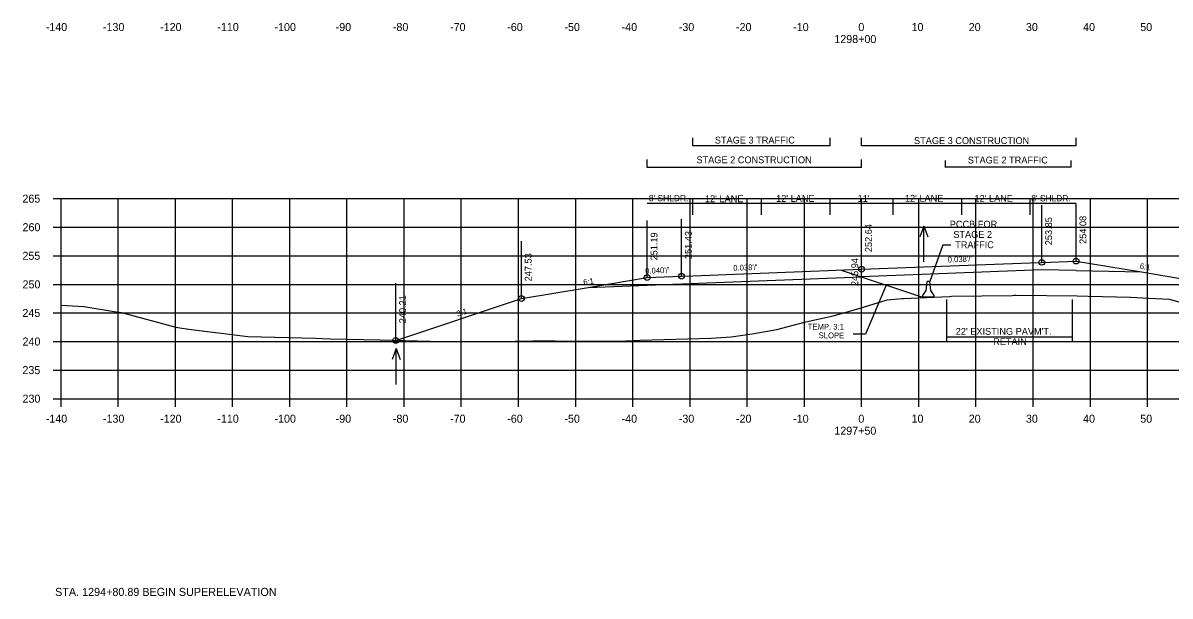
# Model space of a CAD drawing. Extents: x 1342547 to 1344156, y -1532351 to -1517216.
# Drawn here: x 1342556.2 to 1342756.8, y -1520418.8 to -1520318.5 of the extents above; entities that cross this region are included whole.
import ezdxf

# ---------------------------------------------------------------- set-up
doc = ezdxf.new("R2010")
doc.units = 0
for name, color, linetype in [('R_Alt Surface', 7, 'Continuous'), ('R_Axis', 7, 'Continuous'), ('R_Axis Annot', 7, 'Continuous'), ('R_Border Notes', 7, 'Continuous'), ('R_Draft', 7, 'Continuous'), ('R_Exist Surface', 7, 'Continuous'), ('R_Fin Surface', 7, 'Continuous'), ('R_Grid', 7, 'Continuous'), ('R_MOT', 7, 'Continuous'), ('R_No Plot', 7, 'Continuous'), ('R_Water', 7, 'Continuous'), ('R_Xsect Elev', 7, 'Continuous'), ('R_Xsect Slope', 7, 'Continuous')]:
    doc.layers.add(name, color=color, linetype=linetype)

msp = doc.modelspace()

# ---------------------------------------------------------------- linework, layer by layer
at = {"layer": 'R_Alt Surface'}
msp.add_line((1342734.37, -1520361.7), (1342702.87, -1520362.91), dxfattribs=at)
for points in [[(1342665.37, -1520364.35), (1342671.37, -1520364.12), (1342702.87, -1520362.91)], [(1342740.37, -1520361.82), (1342734.37, -1520361.7)], [(1342740.37, -1520361.82), (1342751.84, -1520362.05)], [(1342655.05, -1520364.75), (1342665.37, -1520364.35)]]:
    msp.add_lwpolyline(points, dxfattribs=at)
at = {"layer": 'R_Axis'}
for p, q in [((1342561.47, -1520349.22), (1342562.87, -1520349.22)), ((1342562.87, -1520384.22), (1342562.87, -1520349.22)), ((1342561.47, -1520354.22), (1342562.87, -1520354.22)), ((1342561.47, -1520359.22), (1342562.87, -1520359.22)), ((1342561.47, -1520364.22), (1342562.87, -1520364.22)), ((1342561.47, -1520369.22), (1342562.87, -1520369.22)), ((1342561.47, -1520374.22), (1342562.87, -1520374.22)), ((1342561.47, -1520379.22), (1342562.87, -1520379.22)), ((1342561.47, -1520384.22), (1342562.87, -1520384.22)), ((1342562.87, -1520384.22), (1342842.87, -1520384.22)), ((1342562.87, -1520385.62), (1342562.87, -1520384.22)), ((1342572.87, -1520385.62), (1342572.87, -1520384.22)), ((1342582.87, -1520385.62), (1342582.87, -1520384.22)), ((1342592.87, -1520385.62), (1342592.87, -1520384.22)), ((1342602.87, -1520385.62), (1342602.87, -1520384.22)), ((1342612.87, -1520385.62), (1342612.87, -1520384.22)), ((1342622.87, -1520385.62), (1342622.87, -1520384.22)), ((1342632.87, -1520385.62), (1342632.87, -1520384.22)), ((1342642.87, -1520385.62), (1342642.87, -1520384.22)), ((1342652.87, -1520385.62), (1342652.87, -1520384.22)), ((1342662.87, -1520385.62), (1342662.87, -1520384.22)), ((1342672.87, -1520385.62), (1342672.87, -1520384.22)), ((1342682.87, -1520385.62), (1342682.87, -1520384.22)), ((1342692.87, -1520385.62), (1342692.87, -1520384.22)), ((1342702.87, -1520385.62), (1342702.87, -1520384.22)), ((1342712.87, -1520385.62), (1342712.87, -1520384.22)), ((1342722.87, -1520385.62), (1342722.87, -1520384.22)), ((1342732.87, -1520385.62), (1342732.87, -1520384.22)), ((1342742.87, -1520385.62), (1342742.87, -1520384.22)), ((1342752.87, -1520385.62), (1342752.87, -1520384.22))]:
    msp.add_line(p, q, dxfattribs=at)
at = {"layer": 'R_Draft'}
for p, q in [((1342673.38, -1520340), (1342673.38, -1520338.57)), ((1342697.38, -1520340), (1342697.38, -1520338.57)), ((1342702.87, -1520340), (1342702.87, -1520338.57)), ((1342740.38, -1520340), (1342740.38, -1520338.57)), ((1342697.38, -1520340), (1342673.38, -1520340)), ((1342740.38, -1520340), (1342702.87, -1520340)), ((1342665.37, -1520343.8), (1342665.37, -1520342.36)), ((1342702.87, -1520343.8), (1342702.87, -1520342.36)), ((1342717.53, -1520343.8), (1342717.53, -1520342.56)), ((1342739.53, -1520343.7), (1342739.53, -1520342.56)), ((1342702.87, -1520343.8), (1342665.37, -1520343.8)), ((1342739.53, -1520343.7), (1342717.53, -1520343.7)), ((1342699.28, -1520361.72), (1342713.7, -1520366.53)), ((1342717.69, -1520366.88), (1342717.69, -1520374.08)), ((1342739.69, -1520366.88), (1342739.69, -1520374.08)), ((1342717.69, -1520373.41), (1342739.69, -1520373.41))]:
    msp.add_line(p, q, dxfattribs=at)
for points in [[(1342717.05, -1520357.32), (1342714.82, -1520363.73)], [(1342717.05, -1520357.32), (1342718.49, -1520357.32)]]:
    msp.add_lwpolyline(points, dxfattribs=at)
at = {"layer": 'R_Exist Surface'}
msp.add_lwpolyline([(1342562.87, -1520367.88), (1342566.86, -1520368.07), (1342572.17, -1520368.94), (1342573.42, -1520369.16), (1342582.95, -1520371.69), (1342583.62, -1520371.85), (1342585.21, -1520372.06), (1342595.52, -1520373.35), (1342607.35, -1520373.66), (1342608.56, -1520373.69), (1342610.02, -1520373.72), (1342618.62, -1520373.95), (1342627.45, -1520374.15), (1342640.08, -1520374.2), (1342644.52, -1520374.12), (1342645.01, -1520374.14), (1342645.38, -1520374.09), (1342645.47, -1520374.1), (1342645.55, -1520374.14), (1342645.68, -1520374.11), (1342649.28, -1520374.08), (1342649.63, -1520374.16), (1342661.57, -1520374.11), (1342664.14, -1520373.98), (1342676.55, -1520373.63), (1342680.06, -1520373.4), (1342683.73, -1520372.88), (1342688.04, -1520372.11), (1342693.09, -1520370.78), (1342697.92, -1520369.71), (1342702.6, -1520368.36), (1342707.34, -1520366.92), (1342709.94, -1520366.7), (1342710.2, -1520366.68), (1342718.23, -1520366.32), (1342718.61, -1520366.3), (1342729.18, -1520366.14), (1342729.55, -1520366.13), (1342729.92, -1520366.13), (1342740.56, -1520366.21), (1342742.49, -1520366.27), (1342749.93, -1520366.47), (1342749.93, -1520366.47), (1342753.04, -1520366.63), (1342756.71, -1520366.82), (1342764.98, -1520369.22)], dxfattribs=at)
at = {"layer": 'R_Fin Surface'}
msp.add_lwpolyline([(1342621.4, -1520374.02), (1342643.37, -1520366.69), (1342655.05, -1520364.75), (1342665.37, -1520363.03), (1342671.37, -1520362.79), (1342673.37, -1520362.71), (1342702.87, -1520361.58), (1342732.37, -1520360.45), (1342734.37, -1520360.37), (1342740.37, -1520360.14), (1342751.84, -1520362.05), (1342762.37, -1520363.81), (1342790.77, -1520373.27)], dxfattribs=at)
at = {"layer": 'R_Grid'}
for p, q in [((1342562.87, -1520349.22), (1342842.87, -1520349.22)), ((1342562.87, -1520384.22), (1342562.87, -1520349.22)), ((1342572.87, -1520384.22), (1342572.87, -1520349.22)), ((1342582.87, -1520384.22), (1342582.87, -1520349.22)), ((1342592.87, -1520384.22), (1342592.87, -1520349.22)), ((1342602.87, -1520384.22), (1342602.87, -1520349.22)), ((1342612.87, -1520384.22), (1342612.87, -1520349.22)), ((1342622.87, -1520384.22), (1342622.87, -1520349.22)), ((1342632.87, -1520384.22), (1342632.87, -1520349.22)), ((1342642.87, -1520384.22), (1342642.87, -1520349.22)), ((1342652.87, -1520384.22), (1342652.87, -1520349.22)), ((1342662.87, -1520384.22), (1342662.87, -1520349.22)), ((1342672.87, -1520384.22), (1342672.87, -1520349.22)), ((1342682.87, -1520384.22), (1342682.87, -1520349.22)), ((1342692.87, -1520384.22), (1342692.87, -1520349.22)), ((1342702.87, -1520384.22), (1342702.87, -1520349.22)), ((1342712.87, -1520384.22), (1342712.87, -1520349.22)), ((1342722.87, -1520384.22), (1342722.87, -1520349.22)), ((1342732.87, -1520384.22), (1342732.87, -1520349.22)), ((1342742.87, -1520384.22), (1342742.87, -1520349.22)), ((1342752.87, -1520384.22), (1342752.87, -1520349.22)), ((1342562.87, -1520354.22), (1342842.87, -1520354.22)), ((1342562.87, -1520359.22), (1342842.87, -1520359.22)), ((1342562.87, -1520364.22), (1342842.87, -1520364.22)), ((1342562.87, -1520369.22), (1342842.87, -1520369.22)), ((1342562.87, -1520374.22), (1342842.87, -1520374.22)), ((1342562.87, -1520379.22), (1342842.87, -1520379.22)), ((1342562.87, -1520384.22), (1342842.87, -1520384.22))]:
    msp.add_line(p, q, dxfattribs=at)
at = {"layer": 'R_MOT'}
for p, q in [((1342713.58, -1520366.15), (1342714.15, -1520365.31)), ((1342714.15, -1520365.31), (1342714.32, -1520363.73)), ((1342714.57, -1520363.73), (1342714.32, -1520363.73)), ((1342714.82, -1520363.73), (1342714.57, -1520363.73)), ((1342714.99, -1520365.31), (1342714.82, -1520363.73)), ((1342715.58, -1520366.15), (1342714.99, -1520365.31)), ((1342713.57, -1520366.48), (1342713.58, -1520366.15)), ((1342715.57, -1520366.48), (1342713.57, -1520366.48)), ((1342715.57, -1520366.48), (1342715.58, -1520366.15))]:
    msp.add_line(p, q, dxfattribs=at)
at = {"layer": 'R_No Plot'}
for centre in [(1342702.87, -1520361.58), (1342734.37, -1520360.37), (1342740.37, -1520360.14), (1342665.37, -1520363.03), (1342671.37, -1520362.79), (1342643.37, -1520366.69), (1342621.4, -1520374.02)]:
    msp.add_circle(centre, 0.5, dxfattribs=at)
at = {"layer": 'R_Water'}
for p, q in [((1342713.72, -1520354.01), (1342713.02, -1520355.93)), ((1342713.72, -1520360.29), (1342713.72, -1520354.01)), ((1342713.72, -1520354.01), (1342714.42, -1520355.93)), ((1342621.46, -1520375.45), (1342620.76, -1520377.37)), ((1342621.46, -1520381.73), (1342621.46, -1520375.45)), ((1342621.46, -1520375.45), (1342622.16, -1520377.37))]:
    msp.add_line(p, q, dxfattribs=at)
at = {"layer": 'R_Xsect Elev'}
for p, q in [((1342673.37, -1520352.06), (1342673.37, -1520349.2)), ((1342685.37, -1520352.06), (1342685.37, -1520349.2)), ((1342697.37, -1520352.06), (1342697.37, -1520349.2)), ((1342708.37, -1520352.06), (1342708.37, -1520349.2)), ((1342720.37, -1520352.06), (1342720.37, -1520349.2)), ((1342732.37, -1520352.06), (1342732.37, -1520349.2)), ((1342740.37, -1520350.06), (1342665.37, -1520350.06)), ((1342734.37, -1520360.37), (1342734.37, -1520350.37)), ((1342740.37, -1520360.14), (1342740.37, -1520350.14)), ((1342665.37, -1520363.03), (1342665.37, -1520353.03)), ((1342671.37, -1520362.79), (1342671.37, -1520352.79)), ((1342702.87, -1520361.58), (1342702.87, -1520351.58)), ((1342643.37, -1520366.69), (1342643.37, -1520356.69)), ((1342702.87, -1520368.28), (1342702.87, -1520358.28)), ((1342621.4, -1520374.02), (1342621.4, -1520364.02)), ((1342707.14, -1520364.34), (1342703.56, -1520372.92)), ((1342703.56, -1520372.92), (1342701.42, -1520372.92))]:
    msp.add_line(p, q, dxfattribs=at)

# ---------------------------------------------------------------- texts
at = {"layer": 'R_Axis Annot'}
for s, p in [('-140', (1342560.2, -1520319.9)), ('-130', (1342570.2, -1520319.9)), ('-120', (1342580.2, -1520319.9)), ('-110', (1342590.2, -1520319.9)), ('-100', (1342600.2, -1520319.9)), ('-90', (1342610.9, -1520319.9)), ('-80', (1342620.9, -1520319.9)), ('-70', (1342630.9, -1520319.9)), ('-60', (1342640.9, -1520319.9)), ('-50', (1342650.9, -1520319.9)), ('-40', (1342660.9, -1520319.9)), ('-30', (1342670.9, -1520319.9)), ('-20', (1342680.9, -1520319.9)), ('-10', (1342690.9, -1520319.9)), ('0', (1342702.3, -1520319.9)), ('10', (1342711.6, -1520319.9)), ('20', (1342721.6, -1520319.9)), ('30', (1342731.6, -1520319.9)), ('40', (1342741.6, -1520319.9)), ('50', (1342751.6, -1520319.9)), ('1298+00', (1342698.1, -1520322)), ('265', (1342556.12, -1520349.92)), ('260', (1342556.14, -1520354.92)), ('255', (1342556.12, -1520359.92)), ('250', (1342556.14, -1520364.92)), ('245', (1342556.12, -1520369.92)), ('240', (1342556.14, -1520374.92)), ('235', (1342556.12, -1520379.92)), ('230', (1342556.14, -1520384.92)), ('-140', (1342560.2, -1520388.42)), ('-130', (1342570.2, -1520388.42)), ('-120', (1342580.2, -1520388.42)), ('-110', (1342590.2, -1520388.42)), ('-100', (1342600.2, -1520388.42)), ('-90', (1342610.9, -1520388.42)), ('-80', (1342620.9, -1520388.42)), ('-70', (1342630.9, -1520388.42)), ('-60', (1342640.9, -1520388.42)), ('-50', (1342650.9, -1520388.42)), ('-40', (1342660.9, -1520388.42)), ('-30', (1342670.9, -1520388.42)), ('-20', (1342680.9, -1520388.42)), ('-10', (1342690.9, -1520388.42)), ('0', (1342702.3, -1520388.42)), ('10', (1342711.6, -1520388.42)), ('20', (1342721.6, -1520388.42)), ('30', (1342731.6, -1520388.42)), ('40', (1342741.6, -1520388.42)), ('50', (1342751.6, -1520388.42)), ('1297+50', (1342698.1, -1520390.52))]:
    msp.add_text(s, height=1.4, dxfattribs=at).set_placement(p)
at = {"layer": 'R_Border Notes'}
msp.add_text('STA. 1294+80.89 BEGIN SUPERELEVATION', height=1.41, dxfattribs=at).set_placement((1342561.84, -1520418.73))
at = {"layer": 'R_Draft'}
for s, p in [('STAGE 3 TRAFFIC', (1342677.2, -1520339.58)), ('STAGE 3 CONSTRUCTION', (1342712.03, -1520339.67)), ('STAGE 2 CONSTRUCTION', (1342673.99, -1520343.03)), ('STAGE 2 TRAFFIC', (1342721.44, -1520343.07)), ('PCCB FOR', (1342718.29, -1520354.29)), ('STAGE 2', (1342718.9, -1520356.09)), ('TRAFFIC', (1342719.23, -1520357.89)), ("22' EXISTING PAVM'T.", (1342719.33, -1520373.04)), ('RETAIN', (1342725.87, -1520374.84))]:
    msp.add_text(s, height=1.2, dxfattribs=at).set_placement(p)
at = {"layer": 'R_Xsect Elev'}
for s, height, p in [("8' SHLDR.", 1.1, (1342665.67, -1520349.67)), ("12' LANE", 1.2, (1342675.48, -1520349.84)), ("12' LANE", 1.2, (1342687.91, -1520349.79)), ("11'", 1.2, (1342702.18, -1520349.79)), ("12' LANE", 1.2, (1342710.44, -1520349.76)), ("12' LANE", 1.2, (1342722.61, -1520349.77)), ("8' SHLDR.", 1.1, (1342732.54, -1520349.71))]:
    msp.add_text(s, height=height, dxfattribs=at).set_placement(p)
for s, p in [('253.85', (1342736.17, -1520357.37)), ('254.08', (1342742.17, -1520357.14)), ('251.19', (1342667.17, -1520360.03)), ('251.43', (1342673.17, -1520359.79)), ('252.64', (1342704.67, -1520358.58)), ('247.53', (1342645.17, -1520363.69)), ('245.94', (1342702.27, -1520364.52)), ('240.21', (1342623.2, -1520371.02))]:
    msp.add_text(s, height=1.2, rotation=90, dxfattribs=at).set_placement(p)
at = {"layer": 'R_Xsect Slope'}
for s, rotation, p in [("0.038'/'", 2.1976, (1342717.94, -1520360.4)), ("0.040'/'", 2.2906, (1342665.04, -1520362.37)), ("0.038'/'", 2.2125, (1342680.44, -1520361.85)), ('6:1', 350.5377, (1342751.45, -1520361.48)), ('6:1', 9.4623, (1342654.28, -1520364.37)), ('3:1', 18.4349, (1342632.23, -1520369.88)), ('TEMP. 3:1', 359.6242, (1342693.45, -1520372.11)), ('SLOPE', 359.6242, (1342695.36, -1520373.63))]:
    msp.add_text(s, height=1, rotation=rotation, dxfattribs=at).set_placement(p)

doc.saveas('drawing.dxf')
